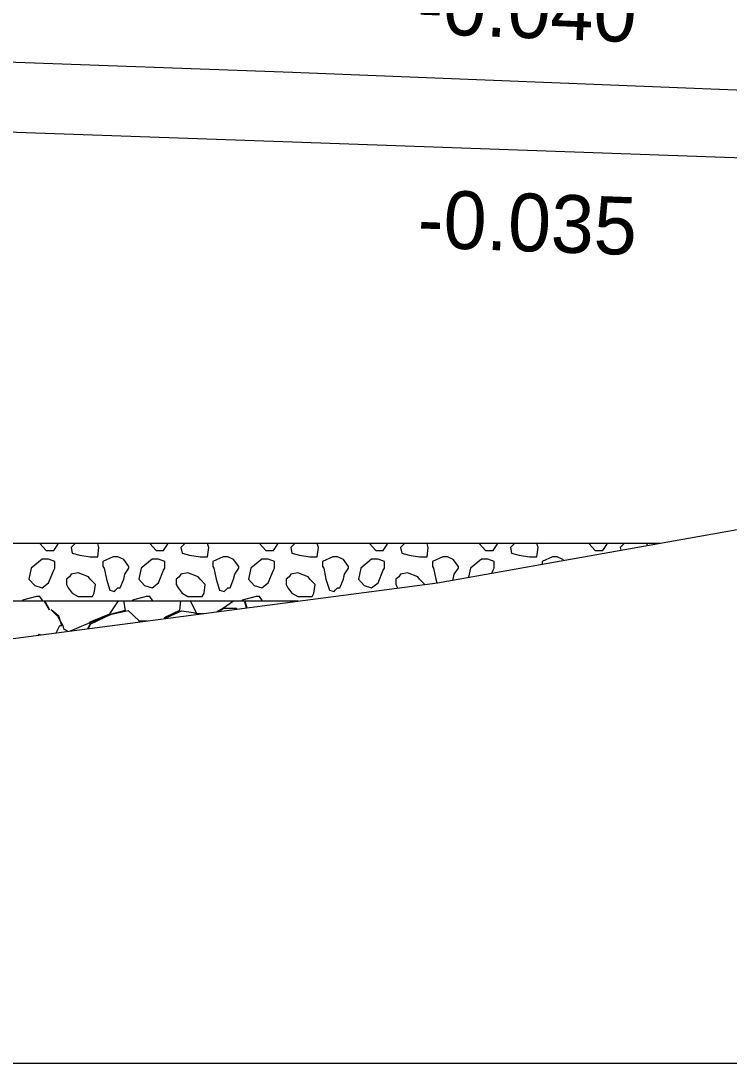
# Model space of a CAD drawing. Extents: x -26 to 4781, y -31 to 24738.
# Drawn here: x 2307.3 to 2319.56, y 8500 to 8518.04 of the extents above; entities that cross this region are included whole.
import ezdxf

# ---------------------------------------------------------------- set-up
doc = ezdxf.new("R2010")
doc.units = 0
for name, color, linetype in [('DESIGN - SHEET - Light Grid', 7, 'Continuous'), ('DESIGN - TRANSPORTATION - Proposed Layout Patterning', 7, 'Continuous'), ('DESIGN - TYPICAL - Finished Grade and Subgrade', 7, 'Continuous'), ('DESIGN - TYPICAL - Finished Grade Slopes Text', 7, 'Continuous'), ('DESIGN - TYPICAL - Subgrade Cross Slope Text', 7, 'Continuous'), ('GEOTECHNICAL – SCRATCH – Level 1', 7, 'Continuous'), ('SURVEY - GROUND - Top of Ground', 7, 'Continuous')]:
    doc.layers.add(name, color=color, linetype=linetype)

msp = doc.modelspace()

# ---------------------------------------------------------------- linework, layer by layer
at = {"layer": 'DESIGN - SHEET - Light Grid'}
msp.add_line((2300, 8500), (2600, 8500), dxfattribs=at)
at = {"layer": 'DESIGN - TRANSPORTATION - Proposed Layout Patterning'}
for p, q in [((2308.632, 8508.996), (2308.62, 8509)), ((2310.532, 8508.996), (2310.52, 8509)), ((2312.432, 8508.996), (2312.42, 8509)), ((2314.332, 8508.996), (2314.32, 8509)), ((2316.232, 8508.996), (2316.22, 8509)), ((2318.132, 8508.996), (2318.12, 8509)), ((2318.142, 8508.962), (2318.132, 8508.996)), ((2307.672, 8508.726), (2307.482, 8508.566)), ((2309.572, 8508.726), (2309.382, 8508.566)), ((2311.472, 8508.726), (2311.282, 8508.566)), ((2313.372, 8508.726), (2313.182, 8508.566)), ((2315.272, 8508.726), (2315.082, 8508.566)), ((2308.722, 8508.596), (2308.742, 8508.566)), ((2310.622, 8508.596), (2310.642, 8508.566)), ((2312.522, 8508.596), (2312.542, 8508.566)), ((2314.422, 8508.596), (2314.442, 8508.566)), ((2315.082, 8508.566), (2315.05, 8508.411)), ((2311.207, 8507.882), (2311.173, 8508)), ((2311.178, 8508), (2311.21, 8507.882))]:
    msp.add_line(p, q, dxfattribs=at)
for points in [[(2307.633, 8509), (2307.632, 8508.996), (2307.742, 8508.876), (2307.872, 8508.876), (2307.942, 8508.976), (2307.954, 8509)], [(2308.248, 8509), (2308.242, 8508.996), (2308.172, 8508.926), (2308.192, 8508.826), (2308.322, 8508.796), (2308.502, 8508.766), (2308.632, 8508.766), (2308.652, 8508.926), (2308.632, 8508.996)], [(2309.533, 8509), (2309.532, 8508.996), (2309.642, 8508.876), (2309.772, 8508.876), (2309.842, 8508.976), (2309.854, 8509)], [(2310.148, 8509), (2310.142, 8508.996), (2310.072, 8508.926), (2310.092, 8508.826), (2310.222, 8508.796), (2310.402, 8508.766), (2310.532, 8508.766), (2310.552, 8508.926), (2310.532, 8508.996)], [(2311.433, 8509), (2311.432, 8508.996), (2311.542, 8508.876), (2311.672, 8508.876), (2311.742, 8508.976), (2311.754, 8509)], [(2312.048, 8509), (2312.042, 8508.996), (2311.972, 8508.926), (2311.992, 8508.826), (2312.122, 8508.796), (2312.302, 8508.766), (2312.432, 8508.766), (2312.452, 8508.926), (2312.432, 8508.996)], [(2313.333, 8509), (2313.332, 8508.996), (2313.442, 8508.876), (2313.572, 8508.876), (2313.642, 8508.976), (2313.654, 8509)], [(2313.948, 8509), (2313.942, 8508.996), (2313.872, 8508.926), (2313.892, 8508.826), (2314.022, 8508.796), (2314.202, 8508.766), (2314.332, 8508.766), (2314.352, 8508.926), (2314.332, 8508.996)], [(2315.233, 8509), (2315.232, 8508.996), (2315.342, 8508.876), (2315.472, 8508.876), (2315.542, 8508.976), (2315.554, 8509)], [(2315.848, 8509), (2315.842, 8508.996), (2315.772, 8508.926), (2315.792, 8508.826), (2315.922, 8508.796), (2316.102, 8508.766), (2316.232, 8508.766), (2316.252, 8508.926), (2316.232, 8508.996)], [(2317.133, 8509), (2317.132, 8508.996), (2317.242, 8508.876), (2317.372, 8508.876), (2317.442, 8508.976), (2317.454, 8509)], [(2317.748, 8509), (2317.742, 8508.996), (2317.672, 8508.926), (2317.682, 8508.88)], [(2307.892, 8508.566), (2307.892, 8508.686), (2307.782, 8508.726), (2307.672, 8508.726)], [(2308.982, 8508.766), (2308.922, 8508.766), (2308.902, 8508.766), (2308.722, 8508.686), (2308.722, 8508.596)], [(2309.172, 8508.566), (2309.172, 8508.596), (2309.082, 8508.716), (2308.982, 8508.766)], [(2309.792, 8508.566), (2309.792, 8508.686), (2309.682, 8508.726), (2309.572, 8508.726)], [(2310.882, 8508.766), (2310.822, 8508.766), (2310.802, 8508.766), (2310.622, 8508.686), (2310.622, 8508.596)], [(2311.072, 8508.566), (2311.072, 8508.596), (2310.982, 8508.716), (2310.882, 8508.766)], [(2311.692, 8508.566), (2311.692, 8508.686), (2311.582, 8508.726), (2311.472, 8508.726)], [(2312.782, 8508.766), (2312.722, 8508.766), (2312.702, 8508.766), (2312.522, 8508.686), (2312.522, 8508.596)], [(2312.972, 8508.566), (2312.972, 8508.596), (2312.882, 8508.716), (2312.782, 8508.766)], [(2313.592, 8508.566), (2313.592, 8508.686), (2313.482, 8508.726), (2313.372, 8508.726)], [(2314.682, 8508.766), (2314.622, 8508.766), (2314.602, 8508.766), (2314.422, 8508.686), (2314.422, 8508.596)], [(2314.872, 8508.566), (2314.872, 8508.596), (2314.782, 8508.716), (2314.682, 8508.766)], [(2315.492, 8508.566), (2315.492, 8508.686), (2315.382, 8508.726), (2315.272, 8508.726)], [(2316.582, 8508.766), (2316.522, 8508.766), (2316.502, 8508.766), (2316.322, 8508.686), (2316.322, 8508.638)], [(2316.691, 8508.704), (2316.682, 8508.716), (2316.582, 8508.766)], [(2307.482, 8508.566), (2307.442, 8508.376), (2307.542, 8508.266), (2307.672, 8508.226), (2307.782, 8508.316), (2307.872, 8508.536), (2307.892, 8508.566)], [(2308.472, 8508.416), (2308.292, 8508.486), (2308.172, 8508.466), (2308.142, 8508.416), (2308.092, 8508.376), (2308.092, 8508.286), (2308.122, 8508.226), (2308.192, 8508.136), (2308.292, 8508.076), (2308.422, 8508.076), (2308.542, 8508.076), (2308.572, 8508.136), (2308.592, 8508.286), (2308.502, 8508.376), (2308.472, 8508.416)], [(2308.742, 8508.566), (2308.782, 8508.376), (2308.842, 8508.186), (2308.922, 8508.166), (2308.942, 8508.186), (2308.982, 8508.226)], [(2308.982, 8508.226), (2309.022, 8508.226), (2309.082, 8508.376), (2309.102, 8508.466), (2309.172, 8508.566)], [(2309.382, 8508.566), (2309.342, 8508.376), (2309.442, 8508.266), (2309.572, 8508.226), (2309.682, 8508.316), (2309.772, 8508.536), (2309.792, 8508.566)], [(2310.372, 8508.416), (2310.192, 8508.486), (2310.072, 8508.466), (2310.042, 8508.416), (2309.992, 8508.376), (2309.992, 8508.286), (2310.022, 8508.226), (2310.092, 8508.136), (2310.192, 8508.076), (2310.322, 8508.076), (2310.442, 8508.076), (2310.472, 8508.136), (2310.492, 8508.286), (2310.402, 8508.376), (2310.372, 8508.416)], [(2310.642, 8508.566), (2310.682, 8508.376), (2310.742, 8508.186), (2310.822, 8508.166), (2310.842, 8508.186), (2310.882, 8508.226)], [(2310.882, 8508.226), (2310.922, 8508.226), (2310.982, 8508.376), (2311.002, 8508.466), (2311.072, 8508.566)], [(2311.282, 8508.566), (2311.242, 8508.376), (2311.342, 8508.266), (2311.472, 8508.226), (2311.582, 8508.316), (2311.672, 8508.536), (2311.692, 8508.566)], [(2312.272, 8508.416), (2312.092, 8508.486), (2311.972, 8508.466), (2311.942, 8508.416), (2311.892, 8508.376), (2311.892, 8508.286), (2311.922, 8508.226), (2311.992, 8508.136), (2312.092, 8508.076), (2312.222, 8508.076), (2312.342, 8508.076), (2312.372, 8508.136), (2312.392, 8508.286), (2312.302, 8508.376), (2312.272, 8508.416)], [(2312.542, 8508.566), (2312.582, 8508.376), (2312.642, 8508.186), (2312.722, 8508.166), (2312.742, 8508.186), (2312.782, 8508.226)], [(2312.782, 8508.226), (2312.822, 8508.226), (2312.882, 8508.376), (2312.902, 8508.466), (2312.972, 8508.566)], [(2313.182, 8508.566), (2313.142, 8508.376), (2313.242, 8508.266), (2313.372, 8508.226), (2313.482, 8508.316), (2313.572, 8508.536), (2313.592, 8508.566)], [(2314.172, 8508.416), (2313.992, 8508.486), (2313.872, 8508.466), (2313.842, 8508.416), (2313.792, 8508.376), (2313.792, 8508.286), (2313.822, 8508.226), (2313.823, 8508.225)], [(2314.442, 8508.566), (2314.482, 8508.376), (2314.502, 8508.314)], [(2314.777, 8508.363), (2314.782, 8508.376), (2314.802, 8508.466), (2314.872, 8508.566)], [(2315.451, 8508.483), (2315.472, 8508.536), (2315.492, 8508.566)], [(2314.292, 8508.287), (2314.202, 8508.376), (2314.172, 8508.416)], [(2307.572, 8508.076), (2307.332, 8508.016), (2307.332, 8508)], [(2307.683, 8508), (2307.632, 8508.076), (2307.572, 8508.076)], [(2307.714, 8508), (2307.719, 8507.998), (2307.799, 8507.848), (2307.719, 8507.988), (2307.719, 8508)], [(2308.463, 8507.522), (2308.499, 8507.598), (2308.499, 8507.638), (2308.839, 8507.778), (2308.992, 8508)], [(2309.078, 8508), (2309.109, 8507.838), (2308.849, 8507.768), (2309.159, 8507.838), (2309.349, 8507.658), (2309.36, 8507.64)], [(2309.472, 8508.076), (2309.232, 8508.016), (2309.232, 8508)], [(2309.583, 8508), (2309.532, 8508.076), (2309.472, 8508.076)], [(2310.065, 8508), (2310.049, 8507.838), (2309.819, 8507.728), (2309.78, 8507.695)], [(2310.478, 8507.786), (2310.349, 8507.778), (2310.238, 8508)], [(2310.98, 8508), (2310.979, 8507.998), (2310.809, 8507.878), (2310.699, 8507.815)], [(2311.372, 8508.076), (2311.132, 8508.016), (2311.132, 8508)], [(2311.483, 8508), (2311.432, 8508.076), (2311.372, 8508.076)], [(2311.994, 8508), (2311.999, 8507.998), (2312.005, 8507.987)], [(2312, 8507.986), (2311.999, 8507.988), (2311.999, 8508)], [(2307.92, 8507.451), (2307.919, 8507.458), (2307.979, 8507.578), (2308.009, 8507.578), (2307.959, 8507.738), (2307.829, 8507.848), (2307.939, 8507.738), (2308.029, 8507.578), (2308.039, 8507.518), (2308.114, 8507.476)], [(2308.162, 8507.483), (2308.499, 8507.628), (2308.849, 8507.758), (2308.509, 8507.598), (2308.466, 8507.522)], [(2309.79, 8507.696), (2310.079, 8507.828), (2310.289, 8507.798), (2310.363, 8507.771)], [(2310.714, 8507.817), (2310.819, 8507.878), (2311.029, 8507.878), (2311.046, 8507.861)], [(2309.361, 8507.64), (2309.349, 8507.658), (2309.479, 8507.658), (2309.484, 8507.656)], [(2307.64, 8507.414), (2307.619, 8507.418), (2307.602, 8507.409)]]:
    msp.add_lwpolyline(points, dxfattribs=at)
at = {"layer": 'DESIGN - TYPICAL - Finished Grade and Subgrade'}
for p, q in [((2302, 8517.511), (2312, 8517.157)), ((2312, 8517.157), (2322, 8516.757)), ((2302, 8516.301), (2312, 8515.947)), ((2312, 8515.947), (2322, 8515.594))]:
    msp.add_line(p, q, dxfattribs=at)
at = {"layer": 'GEOTECHNICAL – SCRATCH – Level 1'}
for p, q in [((2248.946, 8509), (2318.356, 8509)), ((2245.946, 8508), (2312.107, 8508))]:
    msp.add_line(p, q, dxfattribs=at)
at = {"layer": 'SURVEY - GROUND - Top of Ground'}
msp.add_lwpolyline([(2242.783, 8502.834), (2248.858, 8503.206), (2253.993, 8503.535), (2257.472, 8503.675), (2261.959, 8503.957), (2266.455, 8504.253), (2270.459, 8504.568), (2273.125, 8504.748), (2279.12, 8505.167), (2290.167, 8505.937), (2290.7, 8505.972), (2297.309, 8506.468), (2300, 8506.682), (2303.408, 8506.952), (2307.215, 8507.358), (2314.513, 8508.315), (2321.735, 8509.602)], dxfattribs=at)

# ---------------------------------------------------------------- texts
at = {"layer": 'DESIGN - TYPICAL - Finished Grade Slopes Text'}
msp.add_text('-0.040', height=1, rotation=357.7094, dxfattribs=at).set_placement((2314.149, 8517.822))
at = {"layer": 'DESIGN - TYPICAL - Subgrade Cross Slope Text'}
msp.add_text('-0.035', height=1, rotation=357.9749, dxfattribs=at).set_placement((2314.156, 8514.121))

doc.saveas('drawing.dxf')
